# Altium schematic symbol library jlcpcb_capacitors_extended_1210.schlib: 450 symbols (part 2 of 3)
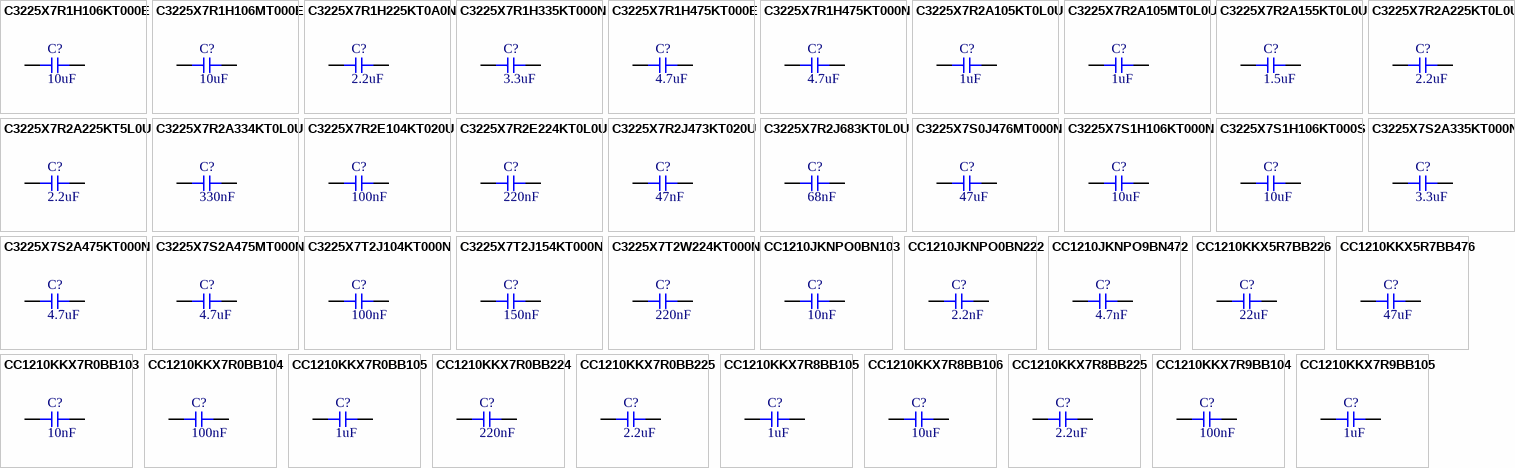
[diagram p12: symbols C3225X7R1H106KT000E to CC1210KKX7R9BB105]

## C3225X7S2A475MT000N
designator C?  Capacitance: 4.7uF  (hidden comment: *)
Capacitor, Ceramic (MLCC), 4.7uF, ±20%, 100V, X7S, ±20%, SMD 1210; Manufacturer: TDK; Manufacturer Part Number: C3225X7S2A475MT000N
footprint CAP-1210 (1210 (3225M) Capacitor)
pins: 1, 2

## C3225X7T2J104KT000N
designator C?  Capacitance: 100nF  (hidden comment: *)
Capacitor, Ceramic (MLCC), 100nF, ±10%, 630V, X7T, ±10%, SMD 1210; Manufacturer: TDK; Manufacturer Part Number: C3225X7T2J104KT000N
footprint CAP-1210 (1210 (3225M) Capacitor)
pins: 1, 2

## C3225X7T2J154KT000N
designator C?  Capacitance: 150nF  (hidden comment: *)
Capacitor, Ceramic (MLCC), 150nF, ±10%, 630V, X7T, ±10%, SMD 1210; Manufacturer: TDK; Manufacturer Part Number: C3225X7T2J154KT000N
footprint CAP-1210 (1210 (3225M) Capacitor)
pins: 1, 2

## C3225X7T2W224KT000N
designator C?  Capacitance: 220nF  (hidden comment: *)
Capacitor, Ceramic (MLCC), 220nF, ±10%, 450V, X7T, ±10%, SMD 1210; Manufacturer: TDK; Manufacturer Part Number: C3225X7T2W224KT000N
footprint CAP-1210 (1210 (3225M) Capacitor)
pins: 1, 2

## CC1210JKNPO0BN103
designator C?  Capacitance: 10nF  (hidden comment: *)
Capacitor, Ceramic (MLCC), 10nF, ±5%, 100V, NP0, ±5%, SMD 1210; Manufacturer: YAGEO; Manufacturer Part Number: CC1210JKNPO0BN103
footprint CAP-1210 (1210 (3225M) Capacitor)
pins: 1, 2

## CC1210JKNPO0BN222
designator C?  Capacitance: 2.2nF  (hidden comment: *)
Capacitor, Ceramic (MLCC), 2.2nF, ±5%, 100V, NP0, ±5%, SMD 1210; Manufacturer: YAGEO; Manufacturer Part Number: CC1210JKNPO0BN222
footprint CAP-1210 (1210 (3225M) Capacitor)
pins: 1, 2

## CC1210JKNPO9BN472
designator C?  Capacitance: 4.7nF  (hidden comment: *)
Capacitor, Ceramic (MLCC), 4.7nF, ±5%, 50V, NP0, ±5%, SMD 1210; Manufacturer: YAGEO; Manufacturer Part Number: CC1210JKNPO9BN472
footprint CAP-1210 (1210 (3225M) Capacitor)
pins: 1, 2

## CC1210KKX5R7BB226
designator C?  Capacitance: 22uF  (hidden comment: *)
Capacitor, Ceramic (MLCC), 22uF, ±10%, 16V, X5R, ±10%, SMD 1210; Manufacturer: YAGEO; Manufacturer Part Number: CC1210KKX5R7BB226
footprint CAP-1210 (1210 (3225M) Capacitor)
pins: 1, 2

## CC1210KKX5R7BB476
designator C?  Capacitance: 47uF  (hidden comment: *)
Capacitor, Ceramic (MLCC), 47uF, ±10%, 16V, X5R, ±10%, SMD 1210; Manufacturer: YAGEO; Manufacturer Part Number: CC1210KKX5R7BB476
footprint CAP-1210 (1210 (3225M) Capacitor)
pins: 1, 2

## CC1210KKX7R0BB103
designator C?  Capacitance: 10nF  (hidden comment: *)
Capacitor, Ceramic (MLCC), 10nF, ±10%, 100V, X7R, ±10%, SMD 1210; Manufacturer: YAGEO; Manufacturer Part Number: CC1210KKX7R0BB103
footprint CAP-1210 (1210 (3225M) Capacitor)
pins: 1, 2

## CC1210KKX7R0BB104
designator C?  Capacitance: 100nF  (hidden comment: *)
Capacitor, Ceramic (MLCC), 100nF, ±10%, 100V, X7R, ±10%, SMD 1210; Manufacturer: YAGEO; Manufacturer Part Number: CC1210KKX7R0BB104
footprint CAP-1210 (1210 (3225M) Capacitor)
pins: 1, 2

## CC1210KKX7R0BB105
designator C?  Capacitance: 1uF  (hidden comment: *)
Capacitor, Ceramic (MLCC), 1uF, ±10%, 100V, X7R, ±10%, SMD 1210; Manufacturer: YAGEO; Manufacturer Part Number: CC1210KKX7R0BB105
footprint CAP-1210 (1210 (3225M) Capacitor)
pins: 1, 2

## CC1210KKX7R0BB224
designator C?  Capacitance: 220nF  (hidden comment: *)
Capacitor, Ceramic (MLCC), 220nF, ±10%, 100V, X7R, ±10%, SMD 1210; Manufacturer: YAGEO; Manufacturer Part Number: CC1210KKX7R0BB224
footprint CAP-1210 (1210 (3225M) Capacitor)
pins: 1, 2

## CC1210KKX7R0BB225
designator C?  Capacitance: 2.2uF  (hidden comment: *)
Capacitor, Ceramic (MLCC), 2.2uF, ±10%, 100V, ±10%, SMD 1210; Manufacturer: YAGEO; Manufacturer Part Number: CC1210KKX7R0BB225
footprint CAP-1210 (1210 (3225M) Capacitor)
pins: 1, 2

## CC1210KKX7R8BB105
designator C?  Capacitance: 1uF  (hidden comment: *)
Capacitor, Ceramic (MLCC), 1uF, ±10%, 25V, X7R, ±10%, SMD 1210; Manufacturer: YAGEO; Manufacturer Part Number: CC1210KKX7R8BB105
footprint CAP-1210 (1210 (3225M) Capacitor)
pins: 1, 2

## CC1210KKX7R8BB106
designator C?  Capacitance: 10uF  (hidden comment: *)
Capacitor, Ceramic (MLCC), 10uF, ±10%, 25V, X7R, ±10%, SMD 1210; Manufacturer: YAGEO; Manufacturer Part Number: CC1210KKX7R8BB106
footprint CAP-1210 (1210 (3225M) Capacitor)
pins: 1, 2

## CC1210KKX7R8BB225
designator C?  Capacitance: 2.2uF  (hidden comment: *)
Capacitor, Ceramic (MLCC), 2.2uF, ±10%, 25V, X7R, ±10%, SMD 1210; Manufacturer: YAGEO; Manufacturer Part Number: CC1210KKX7R8BB225
footprint CAP-1210 (1210 (3225M) Capacitor)
pins: 1, 2

## CC1210KKX7R9BB104
designator C?  Capacitance: 100nF  (hidden comment: *)
Capacitor, Ceramic (MLCC), 100nF, ±10%, 50V, X7R, ±10%, SMD 1210; Manufacturer: YAGEO; Manufacturer Part Number: CC1210KKX7R9BB104
footprint CAP-1210 (1210 (3225M) Capacitor)
pins: 1, 2

## CC1210KKX7R9BB105
designator C?  Capacitance: 1uF  (hidden comment: *)
Capacitor, Ceramic (MLCC), 1uF, ±10%, 50V, X7R, ±10%, SMD 1210; Manufacturer: YAGEO; Manufacturer Part Number: CC1210KKX7R9BB105
footprint CAP-1210 (1210 (3225M) Capacitor)
pins: 1, 2

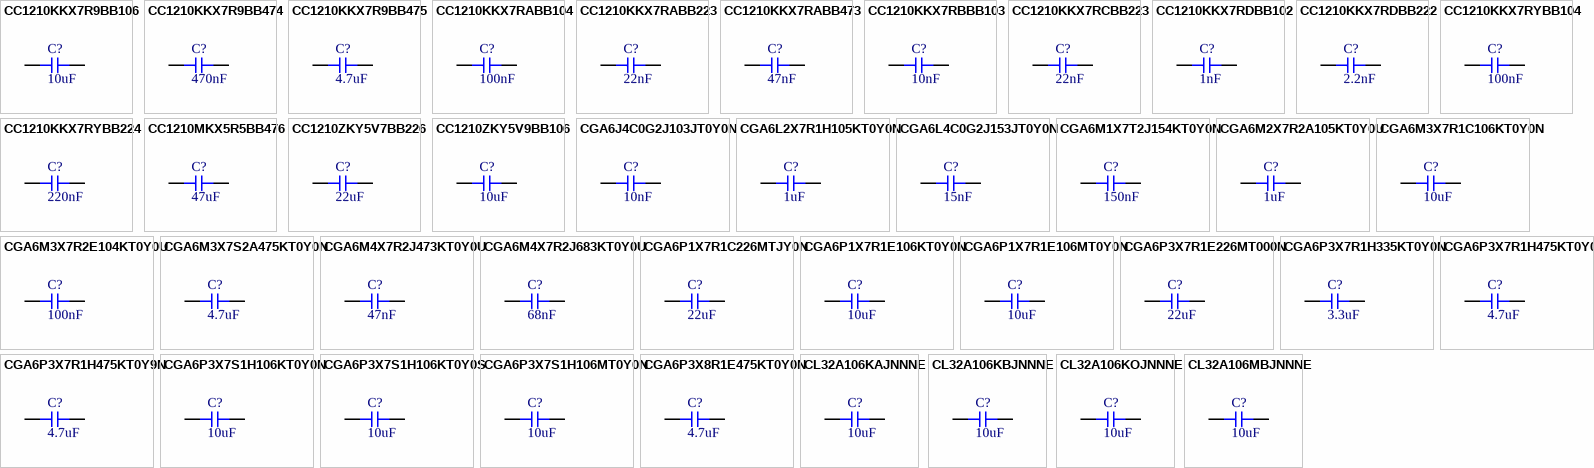
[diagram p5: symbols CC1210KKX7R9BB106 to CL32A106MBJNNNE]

## CC1210KKX7R9BB106
designator C?  Capacitance: 10uF  (hidden comment: *)
Capacitor, Ceramic (MLCC), 10uF, ±10%, 50V, X7R, ±10%, SMD 1210; Manufacturer: YAGEO; Manufacturer Part Number: CC1210KKX7R9BB106
footprint CAP-1210 (1210 (3225M) Capacitor)
pins: 1, 2

## CC1210KKX7R9BB474
designator C?  Capacitance: 470nF  (hidden comment: *)
Capacitor, Ceramic (MLCC), 470nF, ±10%, 50V, X7R, ±10%, SMD 1210; Manufacturer: YAGEO; Manufacturer Part Number: CC1210KKX7R9BB474
footprint CAP-1210 (1210 (3225M) Capacitor)
pins: 1, 2

## CC1210KKX7R9BB475
designator C?  Capacitance: 4.7uF  (hidden comment: *)
Capacitor, Ceramic (MLCC), 4.7uF, ±10%, 50V, X7R, ±10%, SMD 1210; Manufacturer: YAGEO; Manufacturer Part Number: CC1210KKX7R9BB475
footprint CAP-1210 (1210 (3225M) Capacitor)
pins: 1, 2

## CC1210KKX7RABB104
designator C?  Capacitance: 100nF  (hidden comment: *)
Capacitor, Ceramic (MLCC), 100nF, ±10%, 200V, X7R, ±10%, SMD 1210; Manufacturer: YAGEO; Manufacturer Part Number: CC1210KKX7RABB104
footprint CAP-1210 (1210 (3225M) Capacitor)
pins: 1, 2

## CC1210KKX7RABB223
designator C?  Capacitance: 22nF  (hidden comment: *)
Capacitor, Ceramic (MLCC), 22nF, ±10%, 200V, X7R, ±10%, SMD 1210; Manufacturer: YAGEO; Manufacturer Part Number: CC1210KKX7RABB223
footprint CAP-1210 (1210 (3225M) Capacitor)
pins: 1, 2

## CC1210KKX7RABB473
designator C?  Capacitance: 47nF  (hidden comment: *)
Capacitor, Ceramic (MLCC), 47nF, ±10%, 200V, X7R, ±10%, SMD 1210; Manufacturer: YAGEO; Manufacturer Part Number: CC1210KKX7RABB473
footprint CAP-1210 (1210 (3225M) Capacitor)
pins: 1, 2

## CC1210KKX7RBBB103
designator C?  Capacitance: 10nF  (hidden comment: *)
Capacitor, Ceramic (MLCC), 10nF, ±10%, 500V, X7R, ±10%, SMD 1210; Manufacturer: YAGEO; Manufacturer Part Number: CC1210KKX7RBBB103
footprint CAP-1210 (1210 (3225M) Capacitor)
pins: 1, 2

## CC1210KKX7RCBB223
designator C?  Capacitance: 22nF  (hidden comment: *)
Capacitor, Ceramic (MLCC), 22nF, ±10%, 1kV, X7R, ±10%, SMD 1210; Manufacturer: YAGEO; Manufacturer Part Number: CC1210KKX7RCBB223
footprint CAP-1210 (1210 (3225M) Capacitor)
pins: 1, 2

## CC1210KKX7RDBB102
designator C?  Capacitance: 1nF  (hidden comment: *)
Capacitor, Ceramic (MLCC), 1nF, ±10%, 2kV, X7R, ±10%, SMD 1210; Manufacturer: YAGEO; Manufacturer Part Number: CC1210KKX7RDBB102
footprint CAP-1210 (1210 (3225M) Capacitor)
pins: 1, 2

## CC1210KKX7RDBB222
designator C?  Capacitance: 2.2nF  (hidden comment: *)
Capacitor, Ceramic (MLCC), 2.2nF, ±10%, 2kV, X7R, ±10%, SMD 1210; Manufacturer: YAGEO; Manufacturer Part Number: CC1210KKX7RDBB222
footprint CAP-1210 (1210 (3225M) Capacitor)
pins: 1, 2

## CC1210KKX7RYBB104
designator C?  Capacitance: 100nF  (hidden comment: *)
Capacitor, Ceramic (MLCC), 100nF, ±10%, 250V, X7R, ±10%, SMD 1210; Manufacturer: YAGEO; Manufacturer Part Number: CC1210KKX7RYBB104
footprint CAP-1210 (1210 (3225M) Capacitor)
pins: 1, 2

## CC1210KKX7RYBB224
designator C?  Capacitance: 220nF  (hidden comment: *)
Capacitor, Ceramic (MLCC), 220nF, ±10%, 250V, X7R, ±10%, SMD 1210; Manufacturer: YAGEO; Manufacturer Part Number: CC1210KKX7RYBB224
footprint CAP-1210 (1210 (3225M) Capacitor)
pins: 1, 2

## CC1210MKX5R5BB476
designator C?  Capacitance: 47uF  (hidden comment: *)
Capacitor, Ceramic (MLCC), 47uF, ±20%, 6.3V, X5R, ±20%, SMD 1210; Manufacturer: YAGEO; Manufacturer Part Number: CC1210MKX5R5BB476
footprint CAP-1210 (1210 (3225M) Capacitor)
pins: 1, 2

## CC1210ZKY5V7BB226
designator C?  Capacitance: 22uF  (hidden comment: *)
Capacitor, Ceramic (MLCC), 22uF, 16V, Y5V, SMD 1210; Manufacturer: YAGEO; Manufacturer Part Number: CC1210ZKY5V7BB226; Temperature Rating: -20%~+80%
footprint CAP-1210 (1210 (3225M) Capacitor)
pins: 1, 2

## CC1210ZKY5V9BB106
designator C?  Capacitance: 10uF  (hidden comment: *)
Capacitor, Ceramic (MLCC), 10uF, 50V, Y5V, SMD 1210; Manufacturer: YAGEO; Manufacturer Part Number: CC1210ZKY5V9BB106; Temperature Rating: -20%~+80%
footprint CAP-1210 (1210 (3225M) Capacitor)
pins: 1, 2

## CGA6J4C0G2J103JT0Y0N
designator C?  Capacitance: 10nF  (hidden comment: *)
Capacitor, Ceramic (MLCC), 10nF, ±5%, 630V, C0G, ±5%, SMD 1210; Manufacturer: TDK; Manufacturer Part Number: CGA6J4C0G2J103JT0Y0N
footprint CAP-1210 (1210 (3225M) Capacitor)
pins: 1, 2

## CGA6L2X7R1H105KT0Y0N
designator C?  Capacitance: 1uF  (hidden comment: *)
Capacitor, Ceramic (MLCC), 1uF, ±10%, 50V, X7R, ±10%, SMD 1210; Manufacturer: TDK; Manufacturer Part Number: CGA6L2X7R1H105KT0Y0N
footprint CAP-1210 (1210 (3225M) Capacitor)
pins: 1, 2

## CGA6L4C0G2J153JT0Y0N
designator C?  Capacitance: 15nF  (hidden comment: *)
Capacitor, Ceramic (MLCC), 15nF, ±5%, 630V, C0G, ±5%, SMD 1210; Manufacturer: TDK; Manufacturer Part Number: CGA6L4C0G2J153JT0Y0N
footprint CAP-1210 (1210 (3225M) Capacitor)
pins: 1, 2

## CGA6M1X7T2J154KT0Y0N
designator C?  Capacitance: 150nF  (hidden comment: *)
Capacitor, Ceramic (MLCC), 150nF, ±10%, 630V, X7T, ±10%, SMD 1210; Manufacturer: TDK; Manufacturer Part Number: CGA6M1X7T2J154KT0Y0N
footprint CAP-1210 (1210 (3225M) Capacitor)
pins: 1, 2

## CGA6M2X7R2A105KT0Y0U
designator C?  Capacitance: 1uF  (hidden comment: *)
Capacitor, Ceramic (MLCC), 1uF, ±10%, 100V, X7R, ±10%, SMD 1210; Manufacturer: TDK; Manufacturer Part Number: CGA6M2X7R2A105KT0Y0U
footprint CAP-1210 (1210 (3225M) Capacitor)
pins: 1, 2

## CGA6M3X7R1C106KT0Y0N
designator C?  Capacitance: 10uF  (hidden comment: *)
Capacitor, Ceramic (MLCC), 10uF, ±10%, 16V, X7R, ±10%, SMD 1210; Manufacturer: TDK; Manufacturer Part Number: CGA6M3X7R1C106KT0Y0N
footprint CAP-1210 (1210 (3225M) Capacitor)
pins: 1, 2

## CGA6M3X7R2E104KT0Y0U
designator C?  Capacitance: 100nF  (hidden comment: *)
Capacitor, Ceramic (MLCC), 100nF, ±10%, 250V, X7R, ±10%, SMD 1210; Manufacturer: TDK; Manufacturer Part Number: CGA6M3X7R2E104KT0Y0U
footprint CAP-1210 (1210 (3225M) Capacitor)
pins: 1, 2

## CGA6M3X7S2A475KT0Y0N
designator C?  Capacitance: 4.7uF  (hidden comment: *)
Capacitor, Ceramic (MLCC), 4.7uF, ±10%, 100V, X7S, ±10%, SMD 1210; Manufacturer: TDK; Manufacturer Part Number: CGA6M3X7S2A475KT0Y0N
footprint CAP-1210 (1210 (3225M) Capacitor)
pins: 1, 2

## CGA6M4X7R2J473KT0Y0U
designator C?  Capacitance: 47nF  (hidden comment: *)
Capacitor, Ceramic (MLCC), 47nF, ±10%, 630V, X7R, ±10%, SMD 1210; Manufacturer: TDK; Manufacturer Part Number: CGA6M4X7R2J473KT0Y0U
footprint CAP-1210 (1210 (3225M) Capacitor)
pins: 1, 2

## CGA6M4X7R2J683KT0Y0U
designator C?  Capacitance: 68nF  (hidden comment: *)
Capacitor, Ceramic (MLCC), 68nF, ±10%, 630V, X7R, ±10%, SMD 1210; Manufacturer: TDK; Manufacturer Part Number: CGA6M4X7R2J683KT0Y0U
footprint CAP-1210 (1210 (3225M) Capacitor)
pins: 1, 2

## CGA6P1X7R1C226MTJY0N
designator C?  Capacitance: 22uF  (hidden comment: *)
Capacitor, Ceramic (MLCC), 22uF, ±20%, 16V, X7R, ±20%, SMD 1210; Manufacturer: TDK; Manufacturer Part Number: CGA6P1X7R1C226MTJY0N
footprint CAP-1210 (1210 (3225M) Capacitor)
pins: 1, 2

## CGA6P1X7R1E106KT0Y0N
designator C?  Capacitance: 10uF  (hidden comment: *)
Capacitor, Ceramic (MLCC), 10uF, ±10%, 25V, X7R, ±10%, SMD 1210; Manufacturer: TDK; Manufacturer Part Number: CGA6P1X7R1E106KT0Y0N
footprint CAP-1210 (1210 (3225M) Capacitor)
pins: 1, 2

## CGA6P1X7R1E106MT0Y0N
designator C?  Capacitance: 10uF  (hidden comment: *)
Capacitor, Ceramic (MLCC), 10uF, ±20%, 25V, X7R, ±20%, SMD 1210; Manufacturer: TDK; Manufacturer Part Number: CGA6P1X7R1E106MT0Y0N
footprint CAP-1210 (1210 (3225M) Capacitor)
pins: 1, 2

## CGA6P3X7R1E226MT000N
designator C?  Capacitance: 22uF  (hidden comment: *)
Capacitor, Ceramic (MLCC), 22uF, ±20%, 25V, X7R, ±20%, SMD 1210; Manufacturer: TDK; Manufacturer Part Number: CGA6P3X7R1E226MT000N
footprint CAP-1210 (1210 (3225M) Capacitor)
pins: 1, 2

## CGA6P3X7R1H335KT0Y0N
designator C?  Capacitance: 3.3uF  (hidden comment: *)
Capacitor, Ceramic (MLCC), 3.3uF, ±10%, 50V, X7R, ±10%, SMD 1210; Manufacturer: TDK; Manufacturer Part Number: CGA6P3X7R1H335KT0Y0N
footprint CAP-1210 (1210 (3225M) Capacitor)
pins: 1, 2

## CGA6P3X7R1H475KT0Y0N
designator C?  Capacitance: 4.7uF  (hidden comment: *)
Capacitor, Ceramic (MLCC), 4.7uF, ±10%, 50V, X7R, ±10%, SMD 1210; Manufacturer: TDK; Manufacturer Part Number: CGA6P3X7R1H475KT0Y0N
footprint CAP-1210 (1210 (3225M) Capacitor)
pins: 1, 2

## CGA6P3X7R1H475KT0Y9N
designator C?  Capacitance: 4.7uF  (hidden comment: *)
Capacitor, Ceramic (MLCC), 4.7uF, ±10%, 50V, X7R, ±10%, SMD 1210; Manufacturer: TDK; Manufacturer Part Number: CGA6P3X7R1H475KT0Y9N
footprint CAP-1210 (1210 (3225M) Capacitor)
pins: 1, 2

## CGA6P3X7S1H106KT0Y0N
designator C?  Capacitance: 10uF  (hidden comment: *)
Capacitor, Ceramic (MLCC), 10uF, ±10%, 50V, X7S, ±10%, SMD 1210; Manufacturer: TDK; Manufacturer Part Number: CGA6P3X7S1H106KT0Y0N
footprint CAP-1210 (1210 (3225M) Capacitor)
pins: 1, 2

## CGA6P3X7S1H106KT0Y0S
designator C?  Capacitance: 10uF  (hidden comment: *)
Capacitor, Ceramic (MLCC), 10uF, ±10%, 50V, X7S, ±10%, SMD 1210; Manufacturer: TDK; Manufacturer Part Number: CGA6P3X7S1H106KT0Y0S
footprint CAP-1210 (1210 (3225M) Capacitor)
pins: 1, 2

## CGA6P3X7S1H106MT0Y0N
designator C?  Capacitance: 10uF  (hidden comment: *)
Capacitor, Ceramic (MLCC), 10uF, ±20%, 50V, X7S, ±20%, SMD 1210; Manufacturer: TDK; Manufacturer Part Number: CGA6P3X7S1H106MT0Y0N
footprint CAP-1210 (1210 (3225M) Capacitor)
pins: 1, 2

## CGA6P3X8R1E475KT0Y0N
designator C?  Capacitance: 4.7uF  (hidden comment: *)
Capacitor, Ceramic (MLCC), 4.7uF, ±10%, 25V, X8R, ±10%, SMD 1210; Manufacturer: TDK; Manufacturer Part Number: CGA6P3X8R1E475KT0Y0N
footprint CAP-1210 (1210 (3225M) Capacitor)
pins: 1, 2

## CL32A106KAJNNNE
designator C?  Capacitance: 10uF  (hidden comment: *)
Capacitor, Ceramic (MLCC), 10uF, ±10%, 25V, X5R, ±10%, SMD 1210; Manufacturer: Samsung Electro-Mechanics; Manufacturer Part Number: CL32A106KAJNNNE
footprint CAP-1210 (1210 (3225M) Capacitor)
pins: 1, 2

## CL32A106KBJNNNE
designator C?  Capacitance: 10uF  (hidden comment: *)
Capacitor, Ceramic (MLCC), 10uF, ±10%, 50V, X5R, ±10%, SMD 1210; Manufacturer: Samsung Electro-Mechanics; Manufacturer Part Number: CL32A106KBJNNNE
footprint CAP-1210 (1210 (3225M) Capacitor)
pins: 1, 2

## CL32A106KOJNNNE
designator C?  Capacitance: 10uF  (hidden comment: *)
Capacitor, Ceramic (MLCC), 10uF, ±10%, 16V, X5R, ±10%, SMD 1210; Manufacturer: Samsung Electro-Mechanics; Manufacturer Part Number: CL32A106KOJNNNE
footprint CAP-1210 (1210 (3225M) Capacitor)
pins: 1, 2

## CL32A106MBJNNNE
designator C?  Capacitance: 10uF  (hidden comment: *)
Capacitor, Ceramic (MLCC), 10uF, ±20%, 50V, X5R, ±20%, SMD 1210; Manufacturer: Samsung Electro-Mechanics; Manufacturer Part Number: CL32A106MBJNNNE
footprint CAP-1210 (1210 (3225M) Capacitor)
pins: 1, 2

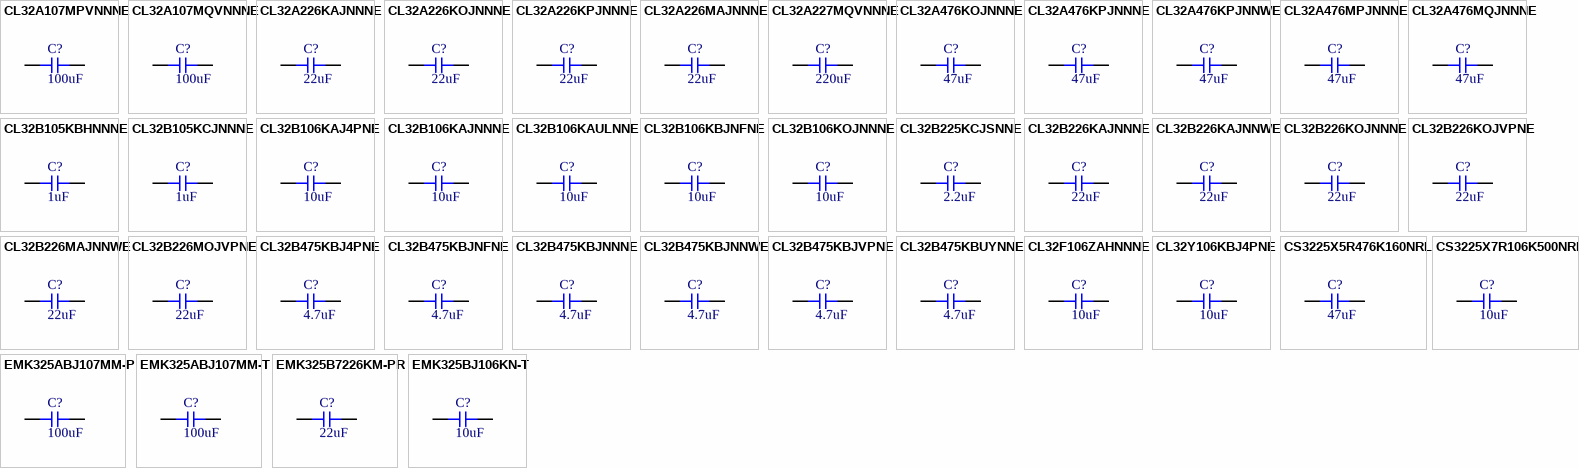
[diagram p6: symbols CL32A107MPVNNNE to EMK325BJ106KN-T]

## CL32A107MPVNNNE
designator C?  Capacitance: 100uF  (hidden comment: *)
Capacitor, Ceramic (MLCC), 100uF, ±20%, 10V, X5R, ±20%, SMD 1210; Manufacturer: Samsung Electro-Mechanics; Manufacturer Part Number: CL32A107MPVNNNE
footprint CAP-1210 (1210 (3225M) Capacitor)
pins: 1, 2

## CL32A107MQVNNNE
designator C?  Capacitance: 100uF  (hidden comment: *)
Capacitor, Ceramic (MLCC), 100uF, ±20%, 6.3V, X5R, ±20%, SMD 1210; Manufacturer: Samsung Electro-Mechanics; Manufacturer Part Number: CL32A107MQVNNNE
footprint CAP-1210 (1210 (3225M) Capacitor)
pins: 1, 2

## CL32A226KAJNNNE
designator C?  Capacitance: 22uF  (hidden comment: *)
Capacitor, Ceramic (MLCC), 22uF, ±10%, 25V, X5R, ±10%, SMD 1210; Manufacturer: Samsung Electro-Mechanics; Manufacturer Part Number: CL32A226KAJNNNE
footprint CAP-1210 (1210 (3225M) Capacitor)
pins: 1, 2

## CL32A226KOJNNNE
designator C?  Capacitance: 22uF  (hidden comment: *)
Capacitor, Ceramic (MLCC), 22uF, ±10%, 16V, X5R, ±10%, SMD 1210; Manufacturer: Samsung Electro-Mechanics; Manufacturer Part Number: CL32A226KOJNNNE
footprint CAP-1210 (1210 (3225M) Capacitor)
pins: 1, 2

## CL32A226KPJNNNE
designator C?  Capacitance: 22uF  (hidden comment: *)
Capacitor, Ceramic (MLCC), 22uF, ±10%, 10V, X5R, ±10%, SMD 1210; Manufacturer: Samsung Electro-Mechanics; Manufacturer Part Number: CL32A226KPJNNNE
footprint CAP-1210 (1210 (3225M) Capacitor)
pins: 1, 2

## CL32A226MAJNNNE
designator C?  Capacitance: 22uF  (hidden comment: *)
Capacitor, Ceramic (MLCC), 22uF, ±20%, 25V, X5R, ±20%, SMD 1210; Manufacturer: Samsung Electro-Mechanics; Manufacturer Part Number: CL32A226MAJNNNE
footprint CAP-1210 (1210 (3225M) Capacitor)
pins: 1, 2

## CL32A227MQVNNNE
designator C?  Capacitance: 220uF  (hidden comment: *)
Capacitor, Ceramic (MLCC), 220uF, ±20%, 6.3V, X5R, ±20%, SMD 1210; Manufacturer: Samsung Electro-Mechanics; Manufacturer Part Number: CL32A227MQVNNNE
footprint CAP-1210 (1210 (3225M) Capacitor)
pins: 1, 2

## CL32A476KOJNNNE
designator C?  Capacitance: 47uF  (hidden comment: *)
Capacitor, Ceramic (MLCC), 47uF, ±10%, 16V, X5R, ±10%, SMD 1210; Manufacturer: Samsung Electro-Mechanics; Manufacturer Part Number: CL32A476KOJNNNE
footprint CAP-1210 (1210 (3225M) Capacitor)
pins: 1, 2

## CL32A476KPJNNNE
designator C?  Capacitance: 47uF  (hidden comment: *)
Capacitor, Ceramic (MLCC), 47uF, ±10%, 10V, X5R, ±10%, SMD 1210; Manufacturer: Samsung Electro-Mechanics; Manufacturer Part Number: CL32A476KPJNNNE
footprint CAP-1210 (1210 (3225M) Capacitor)
pins: 1, 2

## CL32A476KPJNNWE
designator C?  Capacitance: 47uF  (hidden comment: *)
Capacitor, Ceramic (MLCC), 47uF, ±10%, 10V, X5R, ±10%, SMD 1210; Manufacturer: Samsung Electro-Mechanics; Manufacturer Part Number: CL32A476KPJNNWE
footprint CAP-1210 (1210 (3225M) Capacitor)
pins: 1, 2

## CL32A476MPJNNNE
designator C?  Capacitance: 47uF  (hidden comment: *)
Capacitor, Ceramic (MLCC), 47uF, ±20%, 10V, X5R, ±20%, SMD 1210; Manufacturer: Samsung Electro-Mechanics; Manufacturer Part Number: CL32A476MPJNNNE
footprint CAP-1210 (1210 (3225M) Capacitor)
pins: 1, 2

## CL32A476MQJNNNE
designator C?  Capacitance: 47uF  (hidden comment: *)
Capacitor, Ceramic (MLCC), 47uF, ±20%, 6.3V, X5R, ±20%, SMD 1210; Manufacturer: Samsung Electro-Mechanics; Manufacturer Part Number: CL32A476MQJNNNE
footprint CAP-1210 (1210 (3225M) Capacitor)
pins: 1, 2

## CL32B105KBHNNNE
designator C?  Capacitance: 1uF  (hidden comment: *)
Capacitor, Ceramic (MLCC), 1uF, ±10%, 50V, X7R, ±10%, SMD 1210; Manufacturer: Samsung Electro-Mechanics; Manufacturer Part Number: CL32B105KBHNNNE
footprint CAP-1210 (1210 (3225M) Capacitor)
pins: 1, 2

## CL32B105KCJNNNE
designator C?  Capacitance: 1uF  (hidden comment: *)
Capacitor, Ceramic (MLCC), 1uF, ±10%, 100V, X7R, ±10%, SMD 1210; Manufacturer: Samsung Electro-Mechanics; Manufacturer Part Number: CL32B105KCJNNNE
footprint CAP-1210 (1210 (3225M) Capacitor)
pins: 1, 2

## CL32B106KAJ4PNE
designator C?  Capacitance: 10uF  (hidden comment: *)
Capacitor, Ceramic (MLCC), 10uF, ±10%, 25V, X7R, ±10%, SMD 1210; Manufacturer: Samsung Electro-Mechanics; Manufacturer Part Number: CL32B106KAJ4PNE
footprint CAP-1210 (1210 (3225M) Capacitor)
pins: 1, 2

## CL32B106KAJNNNE
designator C?  Capacitance: 10uF  (hidden comment: *)
Capacitor, Ceramic (MLCC), 10uF, ±10%, 25V, X7R, ±10%, SMD 1210; Manufacturer: Samsung Electro-Mechanics; Manufacturer Part Number: CL32B106KAJNNNE
footprint CAP-1210 (1210 (3225M) Capacitor)
pins: 1, 2

## CL32B106KAULNNE
designator C?  Capacitance: 10uF  (hidden comment: *)
Capacitor, Ceramic (MLCC), 10uF, ±10%, 25V, X7R, ±10%, SMD 1210; Manufacturer: Samsung Electro-Mechanics; Manufacturer Part Number: CL32B106KAULNNE
footprint CAP-1210 (1210 (3225M) Capacitor)
pins: 1, 2

## CL32B106KBJNFNE
designator C?  Capacitance: 10uF  (hidden comment: *)
Capacitor, Ceramic (MLCC), 10uF, ±10%, 50V, X7R, ±10%, SMD 1210; Manufacturer: Samsung Electro-Mechanics; Manufacturer Part Number: CL32B106KBJNFNE
footprint CAP-1210 (1210 (3225M) Capacitor)
pins: 1, 2

## CL32B106KOJNNNE
designator C?  Capacitance: 10uF  (hidden comment: *)
Capacitor, Ceramic (MLCC), 10uF, ±10%, 16V, X7R, ±10%, SMD 1210; Manufacturer: Samsung Electro-Mechanics; Manufacturer Part Number: CL32B106KOJNNNE
footprint CAP-1210 (1210 (3225M) Capacitor)
pins: 1, 2

## CL32B225KCJSNNE
designator C?  Capacitance: 2.2uF  (hidden comment: *)
Capacitor, Ceramic (MLCC), 2.2uF, ±10%, 100V, X7R, ±10%, SMD 1210; Manufacturer: Samsung Electro-Mechanics; Manufacturer Part Number: CL32B225KCJSNNE
footprint CAP-1210 (1210 (3225M) Capacitor)
pins: 1, 2

## CL32B226KAJNNNE
designator C?  Capacitance: 22uF  (hidden comment: *)
Capacitor, Ceramic (MLCC), 22uF, ±10%, 25V, X7R, ±10%, SMD 1210; Manufacturer: Samsung Electro-Mechanics; Manufacturer Part Number: CL32B226KAJNNNE
footprint CAP-1210 (1210 (3225M) Capacitor)
pins: 1, 2

## CL32B226KAJNNWE
designator C?  Capacitance: 22uF  (hidden comment: *)
Capacitor, Ceramic (MLCC), 22uF, ±10%, 25V, X7R, ±10%, SMD 1210; Manufacturer: Samsung Electro-Mechanics; Manufacturer Part Number: CL32B226KAJNNWE
footprint CAP-1210 (1210 (3225M) Capacitor)
pins: 1, 2

## CL32B226KOJNNNE
designator C?  Capacitance: 22uF  (hidden comment: *)
Capacitor, Ceramic (MLCC), 22uF, ±10%, 16V, X7R, ±10%, SMD 1210; Manufacturer: Samsung Electro-Mechanics; Manufacturer Part Number: CL32B226KOJNNNE
footprint CAP-1210 (1210 (3225M) Capacitor)
pins: 1, 2

## CL32B226KOJVPNE
designator C?  Capacitance: 22uF  (hidden comment: *)
Capacitor, Ceramic (MLCC), 22uF, ±10%, 16V, X7R, ±10%, SMD 1210; Manufacturer: Samsung Electro-Mechanics; Manufacturer Part Number: CL32B226KOJVPNE
footprint CAP-1210 (1210 (3225M) Capacitor)
pins: 1, 2

## CL32B226MAJNNWE
designator C?  Capacitance: 22uF  (hidden comment: *)
Capacitor, Ceramic (MLCC), 22uF, ±20%, 25V, X7R, ±20%, SMD 1210; Manufacturer: Samsung Electro-Mechanics; Manufacturer Part Number: CL32B226MAJNNWE
footprint CAP-1210 (1210 (3225M) Capacitor)
pins: 1, 2

## CL32B226MOJVPNE
designator C?  Capacitance: 22uF  (hidden comment: *)
Capacitor, Ceramic (MLCC), 22uF, ±20%, 16V, X7R, ±20%, SMD 1210; Manufacturer: Samsung Electro-Mechanics; Manufacturer Part Number: CL32B226MOJVPNE
footprint CAP-1210 (1210 (3225M) Capacitor)
pins: 1, 2

## CL32B475KBJ4PNE
designator C?  Capacitance: 4.7uF  (hidden comment: *)
Capacitor, Ceramic (MLCC), 4.7uF, ±10%, 50V, X7R, ±10%, SMD 1210; Manufacturer: Samsung Electro-Mechanics; Manufacturer Part Number: CL32B475KBJ4PNE
footprint CAP-1210 (1210 (3225M) Capacitor)
pins: 1, 2

## CL32B475KBJNFNE
designator C?  Capacitance: 4.7uF  (hidden comment: *)
Capacitor, Ceramic (MLCC), 4.7uF, ±10%, 50V, X7R, ±10%, SMD 1210; Manufacturer: Samsung Electro-Mechanics; Manufacturer Part Number: CL32B475KBJNFNE
footprint CAP-1210 (1210 (3225M) Capacitor)
pins: 1, 2

## CL32B475KBJNNNE
designator C?  Capacitance: 4.7uF  (hidden comment: *)
Capacitor, Ceramic (MLCC), 4.7uF, ±10%, 50V, X7R, ±10%, SMD 1210; Manufacturer: Samsung Electro-Mechanics; Manufacturer Part Number: CL32B475KBJNNNE
footprint CAP-1210 (1210 (3225M) Capacitor)
pins: 1, 2

## CL32B475KBJNNWE
designator C?  Capacitance: 4.7uF  (hidden comment: *)
Capacitor, Ceramic (MLCC), 4.7uF, ±10%, 50V, X7R, ±10%, SMD 1210; Manufacturer: Samsung Electro-Mechanics; Manufacturer Part Number: CL32B475KBJNNWE
footprint CAP-1210 (1210 (3225M) Capacitor)
pins: 1, 2

## CL32B475KBJVPNE
designator C?  Capacitance: 4.7uF  (hidden comment: *)
Capacitor, Ceramic (MLCC), 4.7uF, ±10%, 50V, X7R, ±10%, SMD 1210; Manufacturer: Samsung Electro-Mechanics; Manufacturer Part Number: CL32B475KBJVPNE
footprint CAP-1210 (1210 (3225M) Capacitor)
pins: 1, 2

## CL32B475KBUYNNE
designator C?  Capacitance: 4.7uF  (hidden comment: *)
Capacitor, Ceramic (MLCC), 4.7uF, ±10%, 50V, X7R, ±10%, SMD 1210; Manufacturer: Samsung Electro-Mechanics; Manufacturer Part Number: CL32B475KBUYNNE
footprint CAP-1210 (1210 (3225M) Capacitor)
pins: 1, 2

## CL32F106ZAHNNNE
designator C?  Capacitance: 10uF  (hidden comment: *)
Capacitor, Ceramic (MLCC), 10uF, 25V, Y5V, SMD 1210; Manufacturer: Samsung Electro-Mechanics; Manufacturer Part Number: CL32F106ZAHNNNE; Temperature Rating: -20%~+80%
footprint CAP-1210 (1210 (3225M) Capacitor)
pins: 1, 2

## CL32Y106KBJ4PNE
designator C?  Capacitance: 10uF  (hidden comment: *)
Capacitor, Ceramic (MLCC), 10uF, ±10%, 50V, X7S, ±10%, SMD 1210; Manufacturer: Samsung Electro-Mechanics; Manufacturer Part Number: CL32Y106KBJ4PNE
footprint CAP-1210 (1210 (3225M) Capacitor)
pins: 1, 2

## CS3225X5R476K160NRL
designator C?  Capacitance: 47uF  (hidden comment: *)
Capacitor, Ceramic (MLCC), 47uF, ±10%, 16V, X5R, ±10%, SMD 1210; Manufacturer: Samwha Capacitor; Manufacturer Part Number: CS3225X5R476K160NRL
footprint CAP-1210 (1210 (3225M) Capacitor)
pins: 1, 2

## CS3225X7R106K500NRL
designator C?  Capacitance: 10uF  (hidden comment: *)
Capacitor, Ceramic (MLCC), 10uF, ±10%, 50V, X7R, ±10%, SMD 1210; Manufacturer: Samwha Capacitor; Manufacturer Part Number: CS3225X7R106K500NRL
footprint CAP-1210 (1210 (3225M) Capacitor)
pins: 1, 2

## EMK325ABJ107MM-P
designator C?  Capacitance: 100uF  (hidden comment: *)
Capacitor, Ceramic (MLCC), 100uF, ±20%, 16V, X5R, ±20%, SMD 1210; Manufacturer: Taiyo Yuden; Manufacturer Part Number: EMK325ABJ107MM-P
footprint CAP-1210 (1210 (3225M) Capacitor)
pins: 1, 2

## EMK325ABJ107MM-T
designator C?  Capacitance: 100uF  (hidden comment: *)
Capacitor, Ceramic (MLCC), 100uF, ±20%, 16V, X5R, ±20%, SMD 1210; Manufacturer: Taiyo Yuden; Manufacturer Part Number: EMK325ABJ107MM-T
footprint CAP-1210 (1210 (3225M) Capacitor)
pins: 1, 2

## EMK325B7226KM-PR
designator C?  Capacitance: 22uF  (hidden comment: *)
Capacitor, Ceramic (MLCC), 22uF, ±10%, 16V, X7R, ±10%, SMD 1210; Manufacturer: Taiyo Yuden; Manufacturer Part Number: EMK325B7226KM-PR
footprint CAP-1210 (1210 (3225M) Capacitor)
pins: 1, 2

## EMK325BJ106KN-T
designator C?  Capacitance: 10uF  (hidden comment: *)
Capacitor, Ceramic (MLCC), 10uF, ±10%, 16V, X5R, ±10%, SMD 1210; Manufacturer: Taiyo Yuden; Manufacturer Part Number: EMK325BJ106KN-T
footprint CAP-1210 (1210 (3225M) Capacitor)
pins: 1, 2

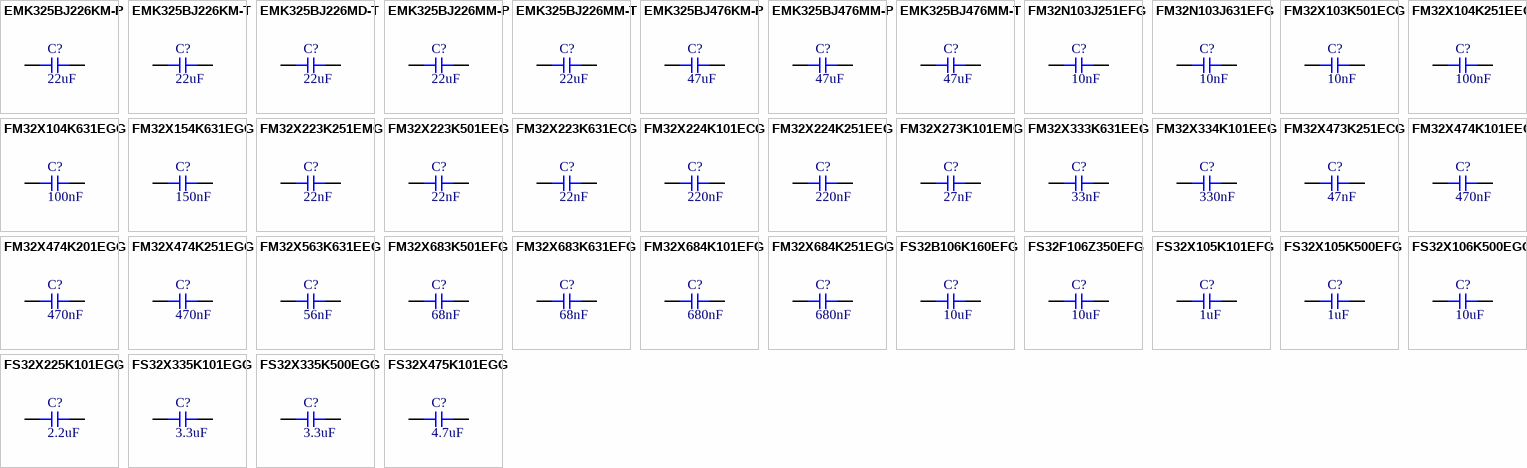
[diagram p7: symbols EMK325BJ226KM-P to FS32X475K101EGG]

## EMK325BJ226KM-P
designator C?  Capacitance: 22uF  (hidden comment: *)
Capacitor, Ceramic (MLCC), 22uF, ±10%, 16V, X5R, ±10%, SMD 1210; Manufacturer: Taiyo Yuden; Manufacturer Part Number: EMK325BJ226KM-P
footprint CAP-1210 (1210 (3225M) Capacitor)
pins: 1, 2

## EMK325BJ226KM-T
designator C?  Capacitance: 22uF  (hidden comment: *)
Capacitor, Ceramic (MLCC), 22uF, ±10%, 16V, X5R, ±10%, SMD 1210; Manufacturer: Taiyo Yuden; Manufacturer Part Number: EMK325BJ226KM-T
footprint CAP-1210 (1210 (3225M) Capacitor)
pins: 1, 2

## EMK325BJ226MD-T
designator C?  Capacitance: 22uF  (hidden comment: *)
Capacitor, Ceramic (MLCC), 22uF, ±20%, 16V, X5R, ±20%, SMD 1210; Manufacturer: Taiyo Yuden; Manufacturer Part Number: EMK325BJ226MD-T
footprint CAP-1210 (1210 (3225M) Capacitor)
pins: 1, 2

## EMK325BJ226MM-P
designator C?  Capacitance: 22uF  (hidden comment: *)
Capacitor, Ceramic (MLCC), 22uF, ±20%, 16V, X5R, ±20%, SMD 1210; Manufacturer: Taiyo Yuden; Manufacturer Part Number: EMK325BJ226MM-P
footprint CAP-1210 (1210 (3225M) Capacitor)
pins: 1, 2

## EMK325BJ226MM-T
designator C?  Capacitance: 22uF  (hidden comment: *)
Capacitor, Ceramic (MLCC), 22uF, ±20%, 16V, X5R, ±20%, SMD 1210; Manufacturer: Taiyo Yuden; Manufacturer Part Number: EMK325BJ226MM-T
footprint CAP-1210 (1210 (3225M) Capacitor)
pins: 1, 2

## EMK325BJ476KM-P
designator C?  Capacitance: 47uF  (hidden comment: *)
Capacitor, Ceramic (MLCC), 47uF, ±10%, 16V, X5R, ±10%, SMD 1210; Manufacturer: Taiyo Yuden; Manufacturer Part Number: EMK325BJ476KM-P
footprint CAP-1210 (1210 (3225M) Capacitor)
pins: 1, 2

## EMK325BJ476MM-P
designator C?  Capacitance: 47uF  (hidden comment: *)
Capacitor, Ceramic (MLCC), 47uF, ±20%, 16V, X5R, ±20%, SMD 1210; Manufacturer: Taiyo Yuden; Manufacturer Part Number: EMK325BJ476MM-P
footprint CAP-1210 (1210 (3225M) Capacitor)
pins: 1, 2

## EMK325BJ476MM-T
designator C?  Capacitance: 47uF  (hidden comment: *)
Capacitor, Ceramic (MLCC), 47uF, ±20%, 16V, X5R, ±20%, SMD 1210; Manufacturer: Taiyo Yuden; Manufacturer Part Number: EMK325BJ476MM-T
footprint CAP-1210 (1210 (3225M) Capacitor)
pins: 1, 2

## FM32N103J251EFG
designator C?  Capacitance: 10nF  (hidden comment: *)
Capacitor, Ceramic (MLCC), 10nF, ±5%, 250V, NP0, ±5%, SMD 1210; Manufacturer: PSA(Prosperity Dielectrics); Manufacturer Part Number: FM32N103J251EFG
footprint CAP-1210 (1210 (3225M) Capacitor)
pins: 1, 2

## FM32N103J631EFG
designator C?  Capacitance: 10nF  (hidden comment: *)
Capacitor, Ceramic (MLCC), 10nF, ±5%, 630V, C0G, ±5%, SMD 1210; Manufacturer: PSA(Prosperity Dielectrics); Manufacturer Part Number: FM32N103J631EFG
footprint CAP-1210 (1210 (3225M) Capacitor)
pins: 1, 2

## FM32X103K501ECG
designator C?  Capacitance: 10nF  (hidden comment: *)
Capacitor, Ceramic (MLCC), 10nF, ±10%, 500V, X7R, ±10%, SMD 1210; Manufacturer: PSA(Prosperity Dielectrics); Manufacturer Part Number: FM32X103K501ECG
footprint CAP-1210 (1210 (3225M) Capacitor)
pins: 1, 2

## FM32X104K251EEG
designator C?  Capacitance: 100nF  (hidden comment: *)
Capacitor, Ceramic (MLCC), 100nF, ±10%, 250V, X7R, ±10%, SMD 1210; Manufacturer: PSA(Prosperity Dielectrics); Manufacturer Part Number: FM32X104K251EEG
footprint CAP-1210 (1210 (3225M) Capacitor)
pins: 1, 2

## FM32X104K631EGG
designator C?  Capacitance: 100nF  (hidden comment: *)
Capacitor, Ceramic (MLCC), 100nF, ±10%, 630V, X7R, ±10%, SMD 1210; Manufacturer: PSA(Prosperity Dielectrics); Manufacturer Part Number: FM32X104K631EGG
footprint CAP-1210 (1210 (3225M) Capacitor)
pins: 1, 2

## FM32X154K631EGG
designator C?  Capacitance: 150nF  (hidden comment: *)
Capacitor, Ceramic (MLCC), 150nF, ±10%, 630V, ±10%, SMD 1210; Manufacturer: PSA(Prosperity Dielectrics); Manufacturer Part Number: FM32X154K631EGG
footprint CAP-1210 (1210 (3225M) Capacitor)
pins: 1, 2

## FM32X223K251EMG
designator C?  Capacitance: 22nF  (hidden comment: *)
Capacitor, Ceramic (MLCC), 22nF, ±10%, 250V, X7R, ±10%, SMD 1210; Manufacturer: PSA(Prosperity Dielectrics); Manufacturer Part Number: FM32X223K251EMG
footprint CAP-1210 (1210 (3225M) Capacitor)
pins: 1, 2

## FM32X223K501EEG
designator C?  Capacitance: 22nF  (hidden comment: *)
Capacitor, Ceramic (MLCC), 22nF, ±10%, 500V, X7R, ±10%, SMD 1210; Manufacturer: PSA(Prosperity Dielectrics); Manufacturer Part Number: FM32X223K501EEG
footprint CAP-1210 (1210 (3225M) Capacitor)
pins: 1, 2

## FM32X223K631ECG
designator C?  Capacitance: 22nF  (hidden comment: *)
Capacitor, Ceramic (MLCC), 22nF, ±10%, 630V, X7R, ±10%, SMD 1210; Manufacturer: PSA(Prosperity Dielectrics); Manufacturer Part Number: FM32X223K631ECG
footprint CAP-1210 (1210 (3225M) Capacitor)
pins: 1, 2

## FM32X224K101ECG
designator C?  Capacitance: 220nF  (hidden comment: *)
Capacitor, Ceramic (MLCC), 220nF, ±10%, 100V, X7R, ±10%, SMD 1210; Manufacturer: PSA(Prosperity Dielectrics); Manufacturer Part Number: FM32X224K101ECG
footprint CAP-1210 (1210 (3225M) Capacitor)
pins: 1, 2

## FM32X224K251EEG
designator C?  Capacitance: 220nF  (hidden comment: *)
Capacitor, Ceramic (MLCC), 220nF, ±10%, 250V, X7R, ±10%, SMD 1210; Manufacturer: PSA(Prosperity Dielectrics); Manufacturer Part Number: FM32X224K251EEG
footprint CAP-1210 (1210 (3225M) Capacitor)
pins: 1, 2

## FM32X273K101EMG
designator C?  Capacitance: 27nF  (hidden comment: *)
Capacitor, Ceramic (MLCC), 27nF, ±10%, 100V, X7R, ±10%, SMD 1210; Manufacturer: PSA(Prosperity Dielectrics); Manufacturer Part Number: FM32X273K101EMG
footprint CAP-1210 (1210 (3225M) Capacitor)
pins: 1, 2

## FM32X333K631EEG
designator C?  Capacitance: 33nF  (hidden comment: *)
Capacitor, Ceramic (MLCC), 33nF, ±10%, 630V, X7R, ±10%, SMD 1210; Manufacturer: PSA(Prosperity Dielectrics); Manufacturer Part Number: FM32X333K631EEG
footprint CAP-1210 (1210 (3225M) Capacitor)
pins: 1, 2

## FM32X334K101EEG
designator C?  Capacitance: 330nF  (hidden comment: *)
Capacitor, Ceramic (MLCC), 330nF, ±10%, 100V, X7R, ±10%, SMD 1210; Manufacturer: PSA(Prosperity Dielectrics); Manufacturer Part Number: FM32X334K101EEG
footprint CAP-1210 (1210 (3225M) Capacitor)
pins: 1, 2

## FM32X473K251ECG
designator C?  Capacitance: 47nF  (hidden comment: *)
Capacitor, Ceramic (MLCC), 47nF, ±10%, 250V, X7R, ±10%, SMD 1210; Manufacturer: PSA(Prosperity Dielectrics); Manufacturer Part Number: FM32X473K251ECG
footprint CAP-1210 (1210 (3225M) Capacitor)
pins: 1, 2

## FM32X474K101EEG
designator C?  Capacitance: 470nF  (hidden comment: *)
Capacitor, Ceramic (MLCC), 470nF, ±10%, 100V, X7R, ±10%, SMD 1210; Manufacturer: PSA(Prosperity Dielectrics); Manufacturer Part Number: FM32X474K101EEG
footprint CAP-1210 (1210 (3225M) Capacitor)
pins: 1, 2

## FM32X474K201EGG
designator C?  Capacitance: 470nF  (hidden comment: *)
Capacitor, Ceramic (MLCC), 470nF, ±10%, 200V, X7R, ±10%, SMD 1210; Manufacturer: PSA(Prosperity Dielectrics); Manufacturer Part Number: FM32X474K201EGG
footprint CAP-1210 (1210 (3225M) Capacitor)
pins: 1, 2

## FM32X474K251EGG
designator C?  Capacitance: 470nF  (hidden comment: *)
Capacitor, Ceramic (MLCC), 470nF, ±10%, 250V, X7R, ±10%, SMD 1210; Manufacturer: PSA(Prosperity Dielectrics); Manufacturer Part Number: FM32X474K251EGG
footprint CAP-1210 (1210 (3225M) Capacitor)
pins: 1, 2

## FM32X563K631EEG
designator C?  Capacitance: 56nF  (hidden comment: *)
Capacitor, Ceramic (MLCC), 56nF, ±10%, 630V, X7R, ±10%, SMD 1210; Manufacturer: PSA(Prosperity Dielectrics); Manufacturer Part Number: FM32X563K631EEG
footprint CAP-1210 (1210 (3225M) Capacitor)
pins: 1, 2

## FM32X683K501EFG
designator C?  Capacitance: 68nF  (hidden comment: *)
Capacitor, Ceramic (MLCC), 68nF, ±10%, 500V, X7R, ±10%, SMD 1210; Manufacturer: PSA(Prosperity Dielectrics); Manufacturer Part Number: FM32X683K501EFG
footprint CAP-1210 (1210 (3225M) Capacitor)
pins: 1, 2

## FM32X683K631EFG
designator C?  Capacitance: 68nF  (hidden comment: *)
Capacitor, Ceramic (MLCC), 68nF, ±10%, 630V, X7R, ±10%, SMD 1210; Manufacturer: PSA(Prosperity Dielectrics); Manufacturer Part Number: FM32X683K631EFG
footprint CAP-1210 (1210 (3225M) Capacitor)
pins: 1, 2

## FM32X684K101EFG
designator C?  Capacitance: 680nF  (hidden comment: *)
Capacitor, Ceramic (MLCC), 680nF, ±10%, 100V, X7R, ±10%, SMD 1210; Manufacturer: PSA(Prosperity Dielectrics); Manufacturer Part Number: FM32X684K101EFG
footprint CAP-1210 (1210 (3225M) Capacitor)
pins: 1, 2

## FM32X684K251EGG
designator C?  Capacitance: 680nF  (hidden comment: *)
Capacitor, Ceramic (MLCC), 680nF, ±10%, 250V, X7R, ±10%, SMD 1210; Manufacturer: PSA(Prosperity Dielectrics); Manufacturer Part Number: FM32X684K251EGG
footprint CAP-1210 (1210 (3225M) Capacitor)
pins: 1, 2

## FS32B106K160EFG
designator C?  Capacitance: 10uF  (hidden comment: *)
Capacitor, Ceramic (MLCC), 10uF, ±10%, 16V, X5R, ±10%, SMD 1210; Manufacturer: PSA(Prosperity Dielectrics); Manufacturer Part Number: FS32B106K160EFG
footprint CAP-1210 (1210 (3225M) Capacitor)
pins: 1, 2

## FS32F106Z350EFG
designator C?  Capacitance: 10uF  (hidden comment: *)
Capacitor, Ceramic (MLCC), 10uF, 35V, Y5V, SMD 1210; Manufacturer: PSA(Prosperity Dielectrics); Manufacturer Part Number: FS32F106Z350EFG; Temperature Rating: -20%~+80%
footprint CAP-1210 (1210 (3225M) Capacitor)
pins: 1, 2

## FS32X105K101EFG
designator C?  Capacitance: 1uF  (hidden comment: *)
Capacitor, Ceramic (MLCC), 1uF, ±10%, 100V, X7R, ±10%, SMD 1210; Manufacturer: PSA(Prosperity Dielectrics); Manufacturer Part Number: FS32X105K101EFG
footprint CAP-1210 (1210 (3225M) Capacitor)
pins: 1, 2

## FS32X105K500EFG
designator C?  Capacitance: 1uF  (hidden comment: *)
Capacitor, Ceramic (MLCC), 1uF, ±10%, 50V, ±10%, SMD 1210; Manufacturer: PSA(Prosperity Dielectrics); Manufacturer Part Number: FS32X105K500EFG
footprint CAP-1210 (1210 (3225M) Capacitor)
pins: 1, 2

## FS32X106K500EGG
designator C?  Capacitance: 10uF  (hidden comment: *)
Capacitor, Ceramic (MLCC), 10uF, ±10%, 50V, X7R, ±10%, SMD 1210; Manufacturer: PSA(Prosperity Dielectrics); Manufacturer Part Number: FS32X106K500EGG
footprint CAP-1210 (1210 (3225M) Capacitor)
pins: 1, 2

## FS32X225K101EGG
designator C?  Capacitance: 2.2uF  (hidden comment: *)
Capacitor, Ceramic (MLCC), 2.2uF, ±10%, 100V, X7R, ±10%, SMD 1210; Manufacturer: PSA(Prosperity Dielectrics); Manufacturer Part Number: FS32X225K101EGG
footprint CAP-1210 (1210 (3225M) Capacitor)
pins: 1, 2

## FS32X335K101EGG
designator C?  Capacitance: 3.3uF  (hidden comment: *)
Capacitor, Ceramic (MLCC), 3.3uF, ±10%, 100V, X7R, ±10%, SMD 1210; Manufacturer: PSA(Prosperity Dielectrics); Manufacturer Part Number: FS32X335K101EGG
footprint CAP-1210 (1210 (3225M) Capacitor)
pins: 1, 2

## FS32X335K500EGG
designator C?  Capacitance: 3.3uF  (hidden comment: *)
Capacitor, Ceramic (MLCC), 3.3uF, ±10%, 50V, ±10%, SMD 1210; Manufacturer: PSA(Prosperity Dielectrics); Manufacturer Part Number: FS32X335K500EGG
footprint CAP-1210 (1210 (3225M) Capacitor)
pins: 1, 2

## FS32X475K101EGG
designator C?  Capacitance: 4.7uF  (hidden comment: *)
Capacitor, Ceramic (MLCC), 4.7uF, ±10%, 100V, X7R, ±10%, SMD 1210; Manufacturer: PSA(Prosperity Dielectrics); Manufacturer Part Number: FS32X475K101EGG
footprint CAP-1210 (1210 (3225M) Capacitor)
pins: 1, 2

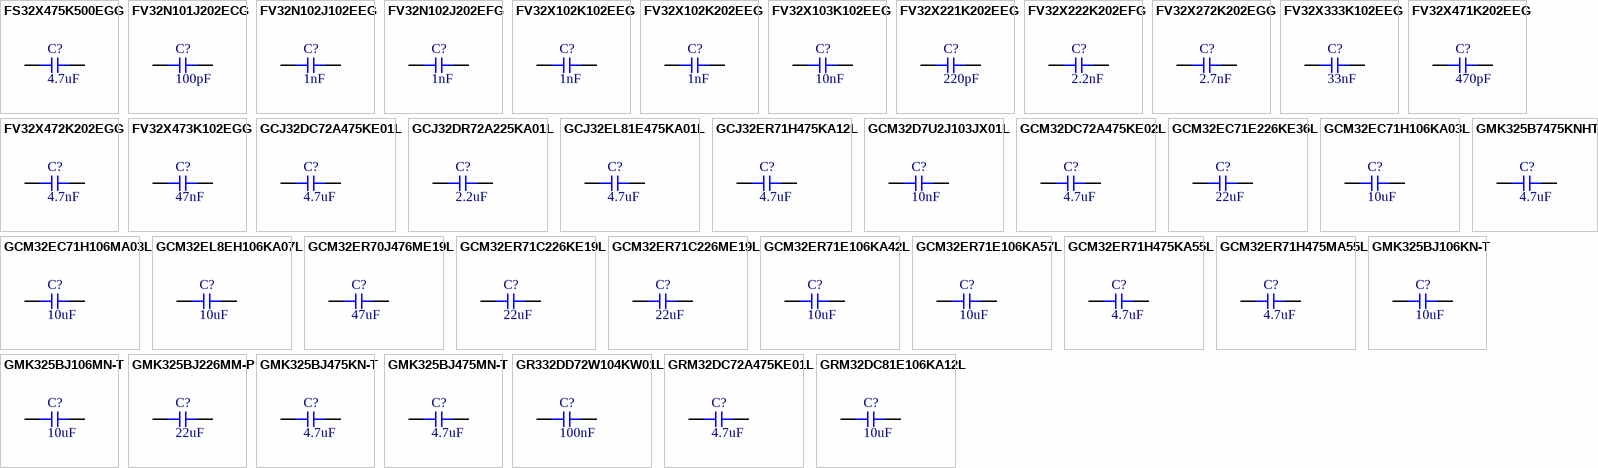
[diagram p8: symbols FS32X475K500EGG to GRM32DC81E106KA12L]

## FS32X475K500EGG
designator C?  Capacitance: 4.7uF  (hidden comment: *)
Capacitor, Ceramic (MLCC), 4.7uF, ±10%, 50V, X7R, ±10%, SMD 1210; Manufacturer: PSA(Prosperity Dielectrics); Manufacturer Part Number: FS32X475K500EGG
footprint CAP-1210 (1210 (3225M) Capacitor)
pins: 1, 2

## FV32N101J202ECG
designator C?  Capacitance: 100pF  (hidden comment: *)
Capacitor, Ceramic (MLCC), 100pF, ±5%, 2kV, ±5%, SMD 1210; Manufacturer: PSA(Prosperity Dielectrics); Manufacturer Part Number: FV32N101J202ECG
footprint CAP-1210 (1210 (3225M) Capacitor)
pins: 1, 2

## FV32N102J102EEG
designator C?  Capacitance: 1nF  (hidden comment: *)
Capacitor, Ceramic (MLCC), 1nF, ±5%, 1kV, ±5%, SMD 1210; Manufacturer: PSA(Prosperity Dielectrics); Manufacturer Part Number: FV32N102J102EEG
footprint CAP-1210 (1210 (3225M) Capacitor)
pins: 1, 2

## FV32N102J202EFG
designator C?  Capacitance: 1nF  (hidden comment: *)
Capacitor, Ceramic (MLCC), 1nF, ±5%, 2kV, C0G, ±5%, SMD 1210; Manufacturer: PSA(Prosperity Dielectrics); Manufacturer Part Number: FV32N102J202EFG
footprint CAP-1210 (1210 (3225M) Capacitor)
pins: 1, 2

## FV32X102K102EEG
designator C?  Capacitance: 1nF  (hidden comment: *)
Capacitor, Ceramic (MLCC), 1nF, ±10%, 1kV, X7R, ±10%, SMD 1210; Manufacturer: PSA(Prosperity Dielectrics); Manufacturer Part Number: FV32X102K102EEG
footprint CAP-1210 (1210 (3225M) Capacitor)
pins: 1, 2

## FV32X102K202EEG
designator C?  Capacitance: 1nF  (hidden comment: *)
Capacitor, Ceramic (MLCC), 1nF, ±10%, 2kV, X7R, ±10%, SMD 1210; Manufacturer: PSA(Prosperity Dielectrics); Manufacturer Part Number: FV32X102K202EEG
footprint CAP-1210 (1210 (3225M) Capacitor)
pins: 1, 2

## FV32X103K102EEG
designator C?  Capacitance: 10nF  (hidden comment: *)
Capacitor, Ceramic (MLCC), 10nF, ±10%, 1kV, X7R, ±10%, SMD 1210; Manufacturer: PSA(Prosperity Dielectrics); Manufacturer Part Number: FV32X103K102EEG
footprint CAP-1210 (1210 (3225M) Capacitor)
pins: 1, 2

## FV32X221K202EEG
designator C?  Capacitance: 220pF  (hidden comment: *)
Capacitor, Ceramic (MLCC), 220pF, ±10%, 2kV, X7R, ±10%, SMD 1210; Manufacturer: PSA(Prosperity Dielectrics); Manufacturer Part Number: FV32X221K202EEG
footprint CAP-1210 (1210 (3225M) Capacitor)
pins: 1, 2

## FV32X222K202EFG
designator C?  Capacitance: 2.2nF  (hidden comment: *)
Capacitor, Ceramic (MLCC), 2.2nF, ±10%, 2kV, X7R, ±10%, SMD 1210; Manufacturer: PSA(Prosperity Dielectrics); Manufacturer Part Number: FV32X222K202EFG
footprint CAP-1210 (1210 (3225M) Capacitor)
pins: 1, 2

## FV32X272K202EGG
designator C?  Capacitance: 2.7nF  (hidden comment: *)
Capacitor, Ceramic (MLCC), 2.7nF, ±10%, 2kV, X7R, ±10%, SMD 1210; Manufacturer: PSA(Prosperity Dielectrics); Manufacturer Part Number: FV32X272K202EGG
footprint CAP-1210 (1210 (3225M) Capacitor)
pins: 1, 2

## FV32X333K102EEG
designator C?  Capacitance: 33nF  (hidden comment: *)
Capacitor, Ceramic (MLCC), 33nF, ±10%, 1kV, ±10%, SMD 1210; Manufacturer: PSA(Prosperity Dielectrics); Manufacturer Part Number: FV32X333K102EEG
footprint CAP-1210 (1210 (3225M) Capacitor)
pins: 1, 2

## FV32X471K202EEG
designator C?  Capacitance: 470pF  (hidden comment: *)
Capacitor, Ceramic (MLCC), 470pF, ±10%, 2kV, X7R, ±10%, SMD 1210; Manufacturer: PSA(Prosperity Dielectrics); Manufacturer Part Number: FV32X471K202EEG
footprint CAP-1210 (1210 (3225M) Capacitor)
pins: 1, 2

## FV32X472K202EGG
designator C?  Capacitance: 4.7nF  (hidden comment: *)
Capacitor, Ceramic (MLCC), 4.7nF, ±10%, 2kV, X7R, ±10%, SMD 1210; Manufacturer: PSA(Prosperity Dielectrics); Manufacturer Part Number: FV32X472K202EGG
footprint CAP-1210 (1210 (3225M) Capacitor)
pins: 1, 2

## FV32X473K102EGG
designator C?  Capacitance: 47nF  (hidden comment: *)
Capacitor, Ceramic (MLCC), 47nF, ±10%, 1kV, X7R, ±10%, SMD 1210; Manufacturer: PSA(Prosperity Dielectrics); Manufacturer Part Number: FV32X473K102EGG
footprint CAP-1210 (1210 (3225M) Capacitor)
pins: 1, 2

## GCJ32DC72A475KE01L
designator C?  Capacitance: 4.7uF  (hidden comment: *)
Capacitor, Ceramic (MLCC), 4.7uF, ±10%, 100V, X7S, ±10%, SMD 1210; Manufacturer: Murata Electronics; Manufacturer Part Number: GCJ32DC72A475KE01L
footprint CAP-1210 (1210 (3225M) Capacitor)
pins: 1, 2

## GCJ32DR72A225KA01L
designator C?  Capacitance: 2.2uF  (hidden comment: *)
Capacitor, Ceramic (MLCC), 2.2uF, ±10%, 100V, X7R, ±10%, SMD 1210; Manufacturer: Murata Electronics; Manufacturer Part Number: GCJ32DR72A225KA01L
footprint CAP-1210 (1210 (3225M) Capacitor)
pins: 1, 2

## GCJ32EL81E475KA01L
designator C?  Capacitance: 4.7uF  (hidden comment: *)
Capacitor, Ceramic (MLCC), 4.7uF, ±10%, 25V, X8L, ±10%, SMD 1210; Manufacturer: Murata Electronics; Manufacturer Part Number: GCJ32EL81E475KA01L
footprint CAP-1210 (1210 (3225M) Capacitor)
pins: 1, 2

## GCJ32ER71H475KA12L
designator C?  Capacitance: 4.7uF  (hidden comment: *)
Capacitor, Ceramic (MLCC), 4.7uF, ±10%, 50V, X7R, ±10%, SMD 1210; Manufacturer: Murata Electronics; Manufacturer Part Number: GCJ32ER71H475KA12L
footprint CAP-1210 (1210 (3225M) Capacitor)
pins: 1, 2

## GCM32D7U2J103JX01L
designator C?  Capacitance: 10nF  (hidden comment: *)
Capacitor, Ceramic (MLCC), 10nF, ±5%, 630V, U2J, ±5%, SMD 1210; Manufacturer: Murata Electronics; Manufacturer Part Number: GCM32D7U2J103JX01L
footprint CAP-1210 (1210 (3225M) Capacitor)
pins: 1, 2

## GCM32DC72A475KE02L
designator C?  Capacitance: 4.7uF  (hidden comment: *)
Capacitor, Ceramic (MLCC), 4.7uF, ±10%, ±10%, SMD 1210; Manufacturer: Murata Electronics; Manufacturer Part Number: GCM32DC72A475KE02L
footprint CAP-1210 (1210 (3225M) Capacitor)
pins: 1, 2

## GCM32EC71E226KE36L
designator C?  Capacitance: 22uF  (hidden comment: *)
Capacitor, Ceramic (MLCC), 22uF, ±10%, 25V, X7S, ±10%, SMD 1210; Manufacturer: Murata Electronics; Manufacturer Part Number: GCM32EC71E226KE36L
footprint CAP-1210 (1210 (3225M) Capacitor)
pins: 1, 2

## GCM32EC71H106KA03L
designator C?  Capacitance: 10uF  (hidden comment: *)
Capacitor, Ceramic (MLCC), 10uF, ±10%, 50V, X7S, ±10%, SMD 1210; Manufacturer: Murata Electronics; Manufacturer Part Number: GCM32EC71H106KA03L
footprint CAP-1210 (1210 (3225M) Capacitor)
pins: 1, 2

## GCM32EC71H106MA03L
designator C?  Capacitance: 10uF  (hidden comment: *)
Capacitor, Ceramic (MLCC), 10uF, ±20%, 50V, X7S, ±20%, SMD 1210; Manufacturer: Murata Electronics; Manufacturer Part Number: GCM32EC71H106MA03L
footprint CAP-1210 (1210 (3225M) Capacitor)
pins: 1, 2

## GCM32EL8EH106KA07L
designator C?  Capacitance: 10uF  (hidden comment: *)
Capacitor, Ceramic (MLCC), 10uF, ±10%, ±10%, SMD 1210; Manufacturer: Murata Electronics; Manufacturer Part Number: GCM32EL8EH106KA07L
footprint CAP-1210 (1210 (3225M) Capacitor)
pins: 1, 2

## GCM32ER70J476ME19L
designator C?  Capacitance: 47uF  (hidden comment: *)
Capacitor, Ceramic (MLCC), 47uF, ±20%, 6.3V, X7R, ±20%, SMD 1210; Manufacturer: Murata Electronics; Manufacturer Part Number: GCM32ER70J476ME19L
footprint CAP-1210 (1210 (3225M) Capacitor)
pins: 1, 2

## GCM32ER71C226KE19L
designator C?  Capacitance: 22uF  (hidden comment: *)
Capacitor, Ceramic (MLCC), 22uF, ±10%, 16V, X7R, ±10%, SMD 1210; Manufacturer: Murata Electronics; Manufacturer Part Number: GCM32ER71C226KE19L
footprint CAP-1210 (1210 (3225M) Capacitor)
pins: 1, 2

## GCM32ER71C226ME19L
designator C?  Capacitance: 22uF  (hidden comment: *)
Capacitor, Ceramic (MLCC), 22uF, ±20%, 16V, X7R, ±20%, SMD 1210; Manufacturer: Murata Electronics; Manufacturer Part Number: GCM32ER71C226ME19L
footprint CAP-1210 (1210 (3225M) Capacitor)
pins: 1, 2

## GCM32ER71E106KA42L
designator C?  Capacitance: 10uF  (hidden comment: *)
Capacitor, Ceramic (MLCC), 10uF, ±10%, 25V, X7R, ±10%, SMD 1210; Manufacturer: Murata Electronics; Manufacturer Part Number: GCM32ER71E106KA42L
footprint CAP-1210 (1210 (3225M) Capacitor)
pins: 1, 2

## GCM32ER71E106KA57L
designator C?  Capacitance: 10uF  (hidden comment: *)
Capacitor, Ceramic (MLCC), 10uF, ±10%, 25V, X7R, ±10%, SMD 1210; Manufacturer: Murata Electronics; Manufacturer Part Number: GCM32ER71E106KA57L
footprint CAP-1210 (1210 (3225M) Capacitor)
pins: 1, 2

## GCM32ER71H475KA55L
designator C?  Capacitance: 4.7uF  (hidden comment: *)
Capacitor, Ceramic (MLCC), 4.7uF, ±10%, 50V, X7R, ±10%, SMD 1210; Manufacturer: Murata Electronics; Manufacturer Part Number: GCM32ER71H475KA55L
footprint CAP-1210 (1210 (3225M) Capacitor)
pins: 1, 2

## GCM32ER71H475MA55L
designator C?  Capacitance: 4.7uF  (hidden comment: *)
Capacitor, Ceramic (MLCC), 4.7uF, ±20%, 50V, X7R, ±20%, SMD 1210; Manufacturer: Murata Electronics; Manufacturer Part Number: GCM32ER71H475MA55L
footprint CAP-1210 (1210 (3225M) Capacitor)
pins: 1, 2

## GMK325B7475KNHTR
designator C?  Capacitance: 4.7uF  (hidden comment: *)
Capacitor, Ceramic (MLCC), 4.7uF, ±10%, 35V, X7R, ±10%, SMD 1210; Manufacturer: Taiyo Yuden; Manufacturer Part Number: GMK325B7475KNHTR
footprint CAP-1210 (1210 (3225M) Capacitor)
pins: 1, 2

## GMK325BJ106KN-T
designator C?  Capacitance: 10uF  (hidden comment: *)
Capacitor, Ceramic (MLCC), 10uF, ±10%, 35V, X5R, ±10%, SMD 1210; Manufacturer: Taiyo Yuden; Manufacturer Part Number: GMK325BJ106KN-T
footprint CAP-1210 (1210 (3225M) Capacitor)
pins: 1, 2

## GMK325BJ106MN-T
designator C?  Capacitance: 10uF  (hidden comment: *)
Capacitor, Ceramic (MLCC), 10uF, ±20%, 35V, X5R, ±20%, SMD 1210; Manufacturer: Taiyo Yuden; Manufacturer Part Number: GMK325BJ106MN-T
footprint CAP-1210 (1210 (3225M) Capacitor)
pins: 1, 2

## GMK325BJ226MM-P
designator C?  Capacitance: 22uF  (hidden comment: *)
Capacitor, Ceramic (MLCC), 22uF, ±20%, 35V, ±20%, SMD 1210; Manufacturer: Taiyo Yuden; Manufacturer Part Number: GMK325BJ226MM-P
footprint CAP-1210 (1210 (3225M) Capacitor)
pins: 1, 2

## GMK325BJ475KN-T
designator C?  Capacitance: 4.7uF  (hidden comment: *)
Capacitor, Ceramic (MLCC), 4.7uF, ±10%, 35V, X5R, ±10%, SMD 1210; Manufacturer: Taiyo Yuden; Manufacturer Part Number: GMK325BJ475KN-T
footprint CAP-1210 (1210 (3225M) Capacitor)
pins: 1, 2

## GMK325BJ475MN-T
designator C?  Capacitance: 4.7uF  (hidden comment: *)
Capacitor, Ceramic (MLCC), 4.7uF, ±20%, 35V, X5R, ±20%, SMD 1210; Manufacturer: Taiyo Yuden; Manufacturer Part Number: GMK325BJ475MN-T
footprint CAP-1210 (1210 (3225M) Capacitor)
pins: 1, 2

## GR332DD72W104KW01L
designator C?  Capacitance: 100nF  (hidden comment: *)
Capacitor, Ceramic (MLCC), 100nF, ±10%, 450V, X7T, ±10%, SMD 1210; Manufacturer: Murata Electronics; Manufacturer Part Number: GR332DD72W104KW01L
footprint CAP-1210 (1210 (3225M) Capacitor)
pins: 1, 2

## GRM32DC72A475KE01L
designator C?  Capacitance: 4.7uF  (hidden comment: *)
Capacitor, Ceramic (MLCC), 4.7uF, ±10%, 100V, X7S, ±10%, SMD 1210; Manufacturer: Murata Electronics; Manufacturer Part Number: GRM32DC72A475KE01L
footprint CAP-1210 (1210 (3225M) Capacitor)
pins: 1, 2

## GRM32DC81E106KA12L
designator C?  Capacitance: 10uF  (hidden comment: *)
Capacitor, Ceramic (MLCC), 10uF, ±10%, 25V, X6S, ±10%, SMD 1210; Manufacturer: Murata Electronics; Manufacturer Part Number: GRM32DC81E106KA12L
footprint CAP-1210 (1210 (3225M) Capacitor)
pins: 1, 2

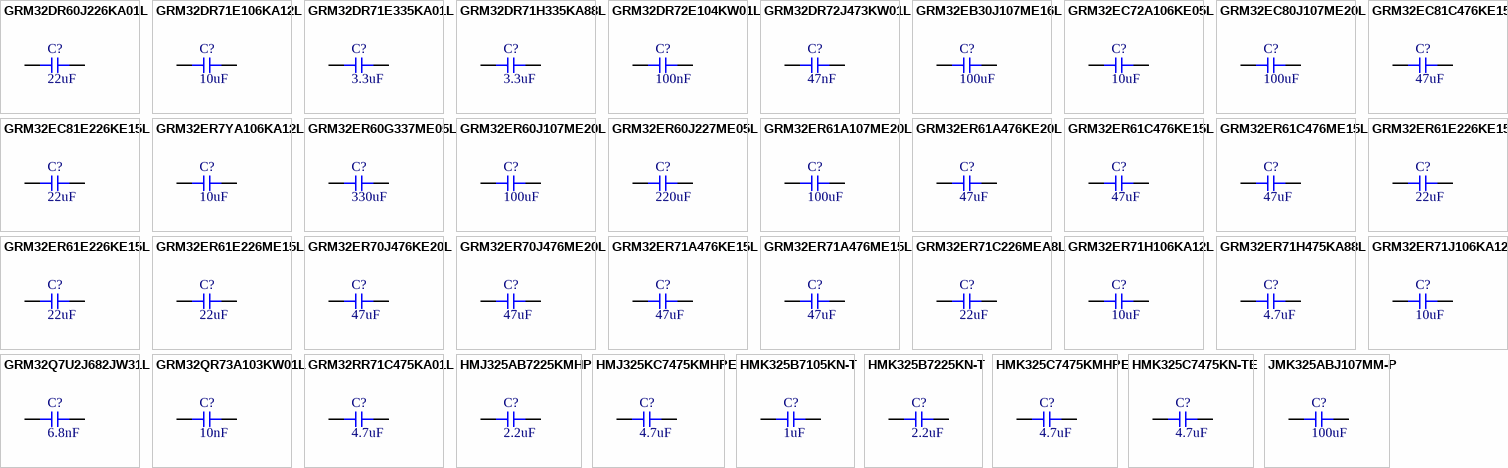
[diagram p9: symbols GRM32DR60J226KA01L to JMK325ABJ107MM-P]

## GRM32DR60J226KA01L
designator C?  Capacitance: 22uF  (hidden comment: *)
Capacitor, Ceramic (MLCC), 22uF, ±10%, 6.3V, X5R, ±10%, SMD 1210; Manufacturer: Murata Electronics; Manufacturer Part Number: GRM32DR60J226KA01L
footprint CAP-1210 (1210 (3225M) Capacitor)
pins: 1, 2

## GRM32DR71E106KA12L
designator C?  Capacitance: 10uF  (hidden comment: *)
Capacitor, Ceramic (MLCC), 10uF, ±10%, 25V, X7R, ±10%, SMD 1210; Manufacturer: Murata Electronics; Manufacturer Part Number: GRM32DR71E106KA12L
footprint CAP-1210 (1210 (3225M) Capacitor)
pins: 1, 2

## GRM32DR71E335KA01L
designator C?  Capacitance: 3.3uF  (hidden comment: *)
Capacitor, Ceramic (MLCC), 3.3uF, ±10%, 25V, X7R, ±10%, SMD 1210; Manufacturer: Murata Electronics; Manufacturer Part Number: GRM32DR71E335KA01L
footprint CAP-1210 (1210 (3225M) Capacitor)
pins: 1, 2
